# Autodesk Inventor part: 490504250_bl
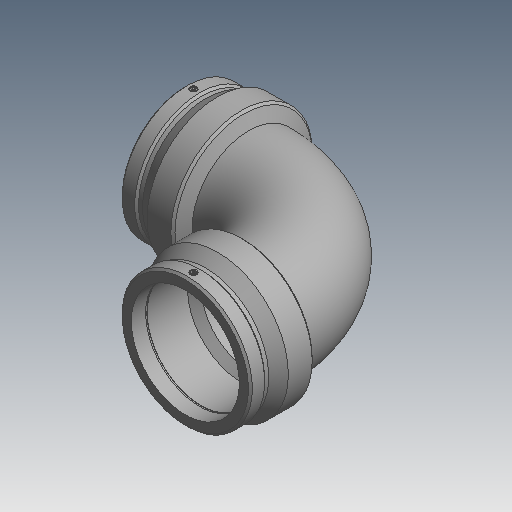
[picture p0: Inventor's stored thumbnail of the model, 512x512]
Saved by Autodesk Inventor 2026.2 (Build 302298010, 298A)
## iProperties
Created: 2017-06
Part Number: 490504250_bl
Material: Generic
Description: PLASSON 90° ELBOW 250
Document SubType Name: Modeling
Designer: KIM
Mass: 55.0731 g
Surface Area: 148.067 cm^2
Volume: 55.0731 cm^3
Density: 1 g/cm^3
Appearance: Default
Author: KIM
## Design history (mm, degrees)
derived "490504.ipt"
feature "Solid1::490504.ipt" dims "ScaleForDerivedMember" = 10
tag "TaggingFeature1"
body "Solid1"
other parameters: "d2" = 327 [user parameter], "d4" = 137.5 [user parameter], "d5" = 294.3 [user parameter], "d8" = 168 deg [user parameter], "d10" = 52 [user parameter], "d11" = 17.33333 [user parameter], "d14" = 17.6296 [user parameter], "d19" = 3.52592 [user parameter], "d20" = 168 deg [user parameter], "d22" = 300.84 [user parameter], "d23" = 327 [user parameter], "d24" = 291.8148 [user parameter], "d29" = 152 [user parameter], "d30" = 15 [user parameter], "d31" = 192.5 [user parameter], "d34" = 5 deg [user parameter], "d35" = 15 [user parameter], "d39" = 5 deg [user parameter], "d41" = 4 [user parameter], "d42" = 14 [user parameter], "d43" = 0 [user parameter], "d45" = 4 [user parameter], "d46" = 14 [user parameter], "d47" = 0 [user parameter], "d50" = 212.5 [user parameter], "d51" = 52 [user parameter], "d54" = 90 deg [user parameter], "d67" = 45 deg [user parameter], "d71" = 90 deg [user parameter], "d75" = 16.35 [user parameter], "d82" = 45 deg [user parameter], "d84" = 294.3 [user parameter], "d87" = 90 deg [user parameter], "d91" = 0 [user parameter], "d93" = 0 [user parameter], "d94" = 90 deg [user parameter], "d101" = 3 [user parameter], "d102" = 0 [user parameter], "d103" = 3 [user parameter], "d104" = 0 [user parameter], "d105" = 37.7 [user parameter], "d106" = 9.425 [user parameter], "d110" = 71.5 [user parameter], "D_" = 327 [user parameter], "A_" = 152 [user parameter], "d_2" = 12 [user parameter]
